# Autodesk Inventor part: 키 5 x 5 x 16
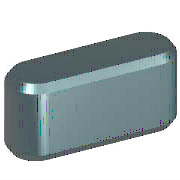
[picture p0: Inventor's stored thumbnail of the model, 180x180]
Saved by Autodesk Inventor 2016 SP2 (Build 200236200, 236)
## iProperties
IsCustomPart: 1
Created: 2012-02
Part Number: 키 5 x 5 x 16
Material: 강철, 연강
Description: 키 및 해당 키홈
Document SubType Name: Modeling
Standard: KS B 1311
Designer: mduedu
Standards Organization: KS
Language: ko-KR
Size Designation: 5 x 5 x 16
Categories: <MemberInstance><Categories><Category DisplayName="샤프트 부품" InternalName="7f7aeb1f-a693-4053-b835-cee3144e0d98" Mnemonic="SHFT"><Category DisplayName="키" Interna
Density: 1 g/cm^3
Appearance: 노란색
Author: mduedu
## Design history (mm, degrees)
workplane "Work Plane1"
workplane "Work Plane2"
sketch "스케치1"
  geometry: L1 (2.5, 2.5)-(13.5, 2.5); L2 (13.5, -2.5)-(2.5, -2.5); L3 (0, 9.4)-(0, -7.4) reference; L4 (-5, 0)-(30, 0) reference; L5 (16, 0)-(16, 7); A1 r 2.5 centre (2.5, 0) between (2.5, 2.5) and (2.5, -2.5); A2 r 2.5 centre (13.5, 0) between (13.5, -2.5) and (13.5, 2.5)
  constraints: 6 end point, 5 point on circle, 4 tangent, 3 point on line, 2 centre point, 1 horizontal, 1 parallel, 1 perpendicular
  dimensions: "d0" = 2.5 radius of A1 (= 0.5 x PB); "d13" = 2.5 radius of A2 (= 0.5 x PB); "d14" = 16 distance between parallel lines of L5 L3 (= NLG)
extrude "본체1" new body sketch "스케치1" taper "d3" = 0 deg; stored distance "d4" = 10
workplane "Work Plane3"
body "Solid1"
chamfer "모따기1" distance "d8" = 0.4 (= PHH); stored, may be unused: second distance "d9" = 0.4 (= PHH), angle "d15" = 45 deg
other parameters: "d1" = -3 (= -PNT), "d2" = 2 (= PH - PNT), "NLG" = 16 [user parameter; used in 3 equation terms], "PB" = 5 [user parameter; used in 2 equation terms], "PNT" = 3 [user parameter; used in 2 equation terms], "PH" = 5 [user parameter; used in 1 equation term], "PHH" = 0.4 [user parameter; used in 2 equation terms], "d10" = 0, "d16" = 0, "d17" = 0, "d18" = 0, "WDMIN" = 12 [user parameter], "PLB2" = 16 (= NLG) [user parameter], "WDMAX" = 17 [user parameter], "PLB1" = 16 (= NLG) [user parameter], "RR" = 0.16 [user parameter], "PUEB" = 2.3 [user parameter]
